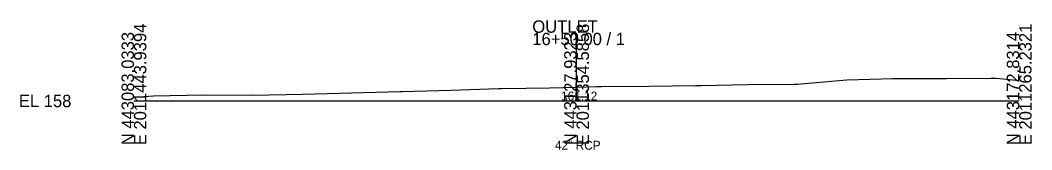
# Model space of a CAD drawing. Extents: x -26 to 1203, y -15 to 9526.
# Drawn here: x -25.7 to 202.8, y 6489 to 6518.3 of the extents above; entities that cross this region are included whole.
import ezdxf

# ---------------------------------------------------------------- set-up
doc = ezdxf.new("R2010")
doc.units = 0
for name, color, linetype in [('Exist Cross Section Cell', 7, 'Continuous'), ('Exist XS Center Line Elevation Label', 7, 'Continuous'), ('Exist XS Ground Line', 7, 'Continuous'), ('Prop XSC Text', 7, 'Continuous')]:
    doc.layers.add(name, color=color, linetype=linetype)

msp = doc.modelspace()

# ---------------------------------------------------------------- linework, layer by layer
at = {"layer": 'Exist Cross Section Cell'}
for p, q in [((100, 6500), (100, 6515.43)), ((0, 6500), (100, 6500)), ((100, 6500), (200, 6500))]:
    msp.add_line(p, q, dxfattribs=at)
at = {"layer": 'Exist XS Ground Line'}
msp.add_lwpolyline([(0, 6500.89), (4.41, 6501.14), (15.68, 6501.36), (26.79, 6501.32), (38.18, 6501.53), (49.17, 6501.83), (60.06, 6502.14), (60.37, 6502.15), (60.67, 6502.16), (71.56, 6502.48), (82.33, 6502.8), (82.75, 6502.81), (83.17, 6502.81), (93.94, 6502.94), (100, 6503.12), (104.61, 6503.25), (105.13, 6503.27), (105.66, 6503.27), (116.32, 6503.32), (126.88, 6503.51), (127.52, 6503.51), (128.16, 6503.53), (138.71, 6503.76), (149.15, 6503.8), (149.9, 6503.81), (150.65, 6503.86), (161.09, 6504.76), (171.42, 6505.07), (172.28, 6505.11), (173.15, 6505.11), (183.47, 6505.09), (193.69, 6505.14), (194.66, 6505.13), (195.64, 6505.06), (200, 6504.61)], dxfattribs=at)

# ---------------------------------------------------------------- texts
at = {"layer": 'Exist Cross Section Cell'}
for s, p in [('OUTLET', (90, 6515.43)), ('16+50.00 / 1', (90, 6512.63)), ('EL 158', (-26, 6498.6))]:
    msp.add_text(s, height=2.8, dxfattribs=at).set_placement(p)
for s, p in [('E 2011443.9394', (2.8, 6490)), ('E 2011354.5858', (102.8, 6490)), ('N 443172.8314', (200, 6490)), ('E 2011265.2321', (202.8, 6490)), ('N 443083.0333', (0, 6490)), ('N 443127.9323', (100, 6490))]:
    msp.add_text(s, height=2.8, rotation=90, dxfattribs=at).set_placement(p)
at = {"layer": 'Exist XS Center Line Elevation Label'}
msp.add_text('161.12', height=2, dxfattribs=at).set_placement((96.5, 6500.12))
at = {"layer": 'Prop XSC Text'}
msp.add_text('42" RCP', height=2, dxfattribs=at).set_placement((95.12, 6488.99))

doc.saveas('drawing.dxf')
